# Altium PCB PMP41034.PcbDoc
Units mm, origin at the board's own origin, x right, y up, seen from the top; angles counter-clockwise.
Board outline 30 x 15 mm, 2 copper layers (Top Layer, Bottom Layer), stack 1.575 mm thick; 22 components, 16 nets, 63 pads, 18 vias.
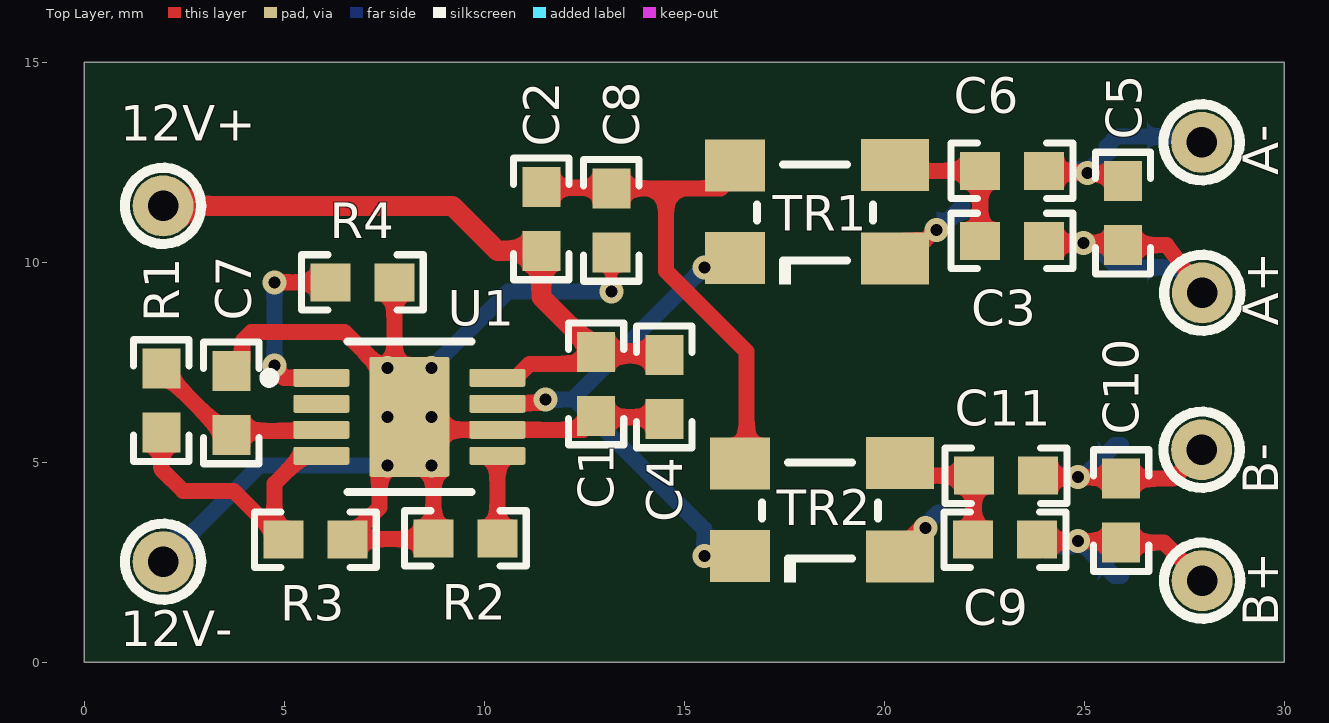
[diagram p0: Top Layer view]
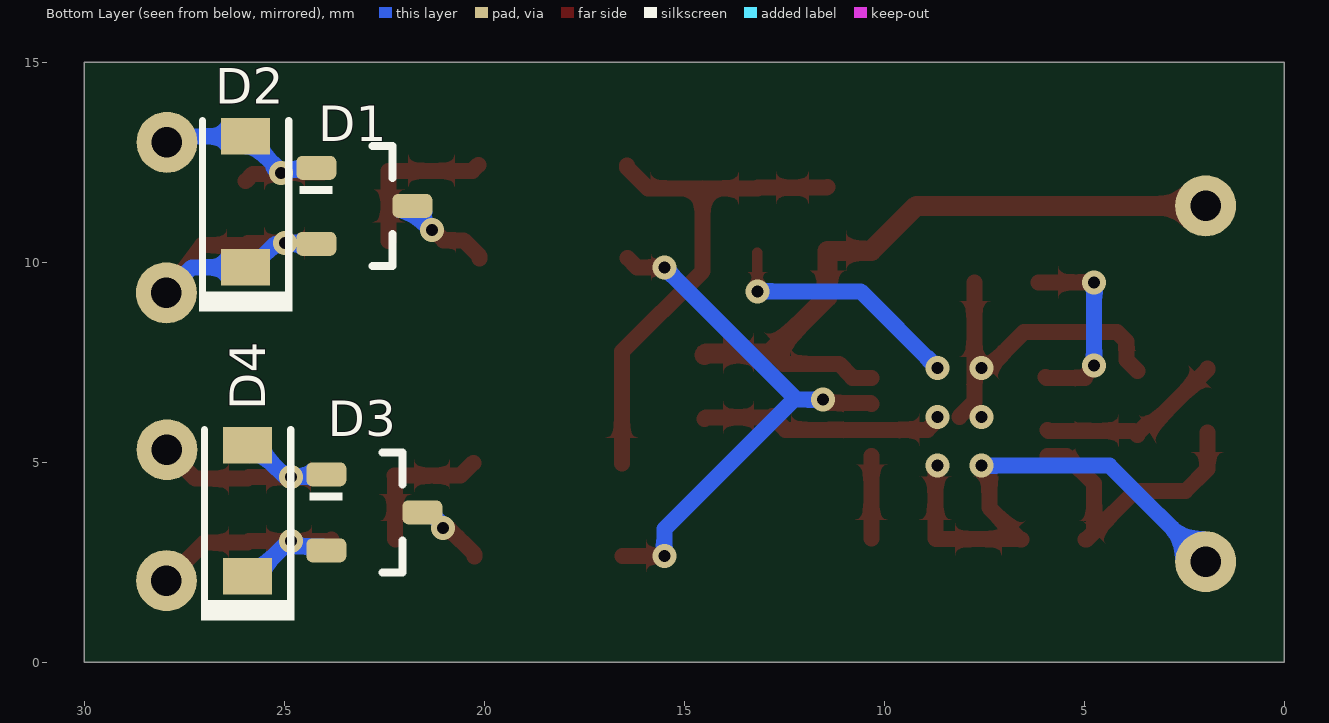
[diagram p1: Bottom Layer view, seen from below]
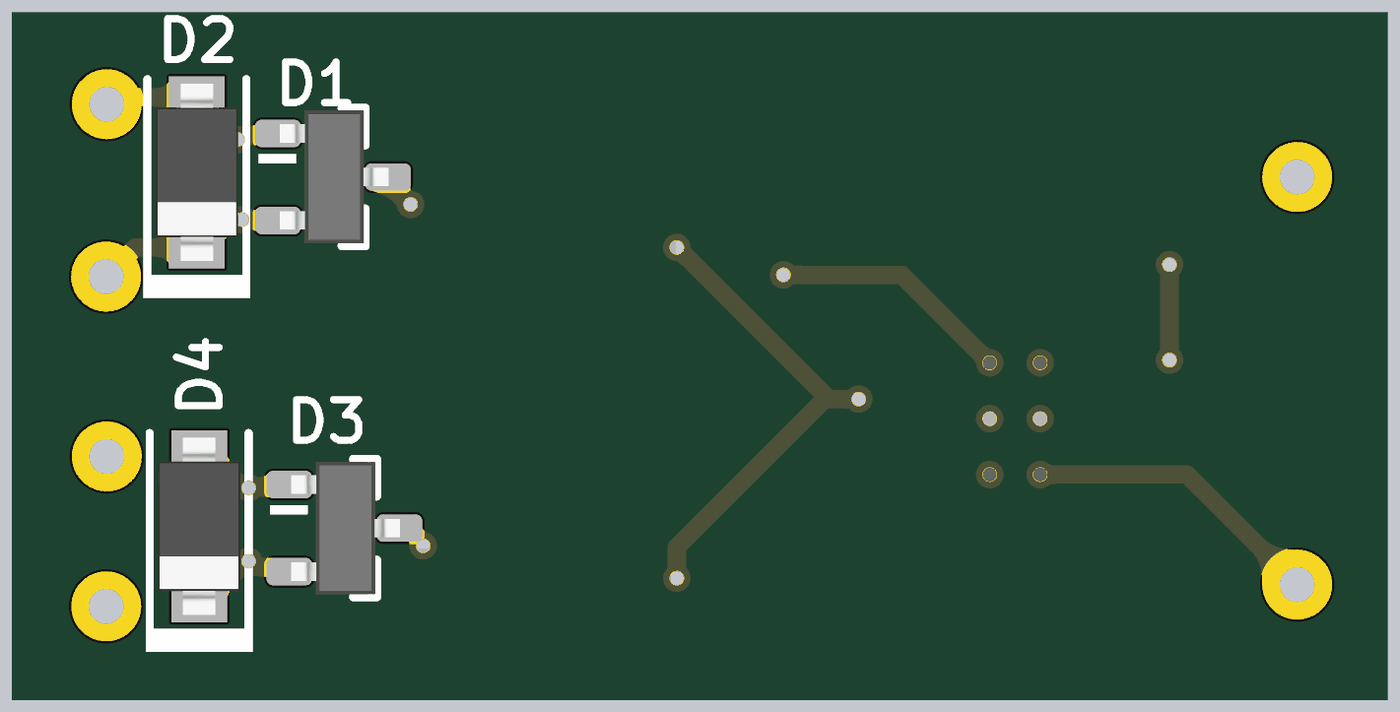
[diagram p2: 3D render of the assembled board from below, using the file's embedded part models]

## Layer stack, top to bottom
Top Solder: solder mask 0.0102, Solder Resist, Dk 3.5
Top Layer: signal copper 0.0356
Dielectric1: core 1.5037, FR-4 High Tg, Dk 4.8
Bottom Layer: signal copper 0.0356
Bottom Solder: solder mask 0.0102, Solder Resist, Dk 3.5

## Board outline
0,0 30,0 30,15 0,15

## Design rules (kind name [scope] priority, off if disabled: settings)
AcuteAngle [All] p1: minimum=4.50000000000000E+0001 checktracksonly=FALSE
AssemblyTestPointUsage [All] p1: valid=2
BoardOutlineClearance BoardOutlineClearance_MountingHoles [OnCopper and InComponentClass('Mounting Holes')] p1: gap=1 ignorepadtopadclearanceinfootprint=FALSE
BoardOutlineClearance BoardOutlineClearance_Poly [OnCopper and IsPoly] p2: gap=0.635 ignorepadtopadclearanceinfootprint=FALSE
BoardOutlineClearance [OnCopper and Not InComponentClass('Logo') and not InComponentClass('FiducialMark') and not InRegion(1000,500,4000,800) and not InPoly] p3: gap=1.016 ignorepadtopadclearanceinfootprint=FALSE
Clearance Clearance_Keepouts [((IsTrack Or IsArc) And Not InPoly) And IsFree and IsKeepOut vs ((IsTrack Or IsArc) And Not InPoly) And IsFree and IsKeepOut] p1: gap=0 ignorepadtopadclearanceinfootprint=FALSE
Clearance Clearance_Poly [InPolygon] p2: gap=0.254 ignorepadtopadclearanceinfootprint=TRUE
Clearance Clearance_FiducialMark [IsKeepOut and InComponentClass('FiducialMark') vs IsPad and InComponentClass('FiducialMark')] p3: gap=0 ignorepadtopadclearanceinfootprint=FALSE
Clearance [All] p4: gap=0.2 ignorepadtopadclearanceinfootprint=TRUE
ComponentClearance ComponentClearance_MountingHoles_FiducialMarks [InComponentClass('Mounting Holes') vs InComponentClass('FiducialMark')] p1 off: gap=1.27 collisioncheckmode=3 verticalgap=0.254 showdistances=FALSE
ComponentClearance ComponentClearance_Shunt [InComponentClass('Header') vs InComponentClass('Shunt')] p2 off: gap=0 collisioncheckmode=3 verticalgap=0 showdistances=FALSE
ComponentClearance ComponentClearance_Logo [InComponentClass('Logo')] p3 off: gap=0.762 collisioncheckmode=3 verticalgap=0.254 showdistances=FALSE
ComponentClearance ComponentClearance_ScrewToNut [(HasFootprint('NY PMS 440 0025 PH')) vs (HasFootprint('Keystone_1902C'))] p4 off: gap=0.127 collisioncheckmode=3 verticalgap=0.254 showdistances=FALSE
ComponentClearance ComponentClearance_MountingHoles [InComponentClass('Mounting Holes')] p5 off: gap=2.54 collisioncheckmode=3 verticalgap=2540 showdistances=FALSE
ComponentClearance ComponentClearance_SmallPassives [HasFootprint('0201*') or HasFootprint('0402*') or HasFootprint('0508') or HasFootprint('0603*') or HasFootprint('0612') or HasFootprint('0805*') or HasFootprint('0815*') or HasFootprint('0830*') or HasFootprint('1206*') or HasFootprint('1210*') or HasFootprint('1808*') or HasFootprint('1812*') or HasFootprint('1825*') or HasFootprint('2010*') or HasFootprint('2220*') or HasFootprint('2225*') or HasFootprint('2512*') or HasFootprint('2728*') or HasFootprint('3518*') vs HasFootprint('0201*') or HasFootprint('0402*') or HasFootprint('0508') or HasFootprint('0603*') or HasFootprint('0612') or HasFootprint('0805*') or HasFootprint('0815*') or HasFootprint('0830*') or HasFootprint('1206*') or HasFootprint('1210*') or HasFootprint('1808*') or HasFootprint('1812*') or HasFootprint('1825*') or HasFootprint('2010*') or HasFootprint('2220*') or HasFootprint('2225*') or HasFootprint('2512*') or HasFootprint('2728*') or HasFootprint('3518*')] p6 off: gap=0.38 collisioncheckmode=3 verticalgap=0.254 showdistances=FALSE
ComponentClearance ComponentClearance_THtoSMT [IsThruComponent vs IsSMTComponent] p7 off: gap=0.762 collisioncheckmode=3 verticalgap=0.762 showdistances=FALSE
ComponentClearance ComponentClearance_THtoTH [IsThruComponent vs IsThruComponent] p8 off: gap=0.508 collisioncheckmode=3 verticalgap=0.762 showdistances=FALSE
ComponentClearance [All] p9 off: gap=0.508 collisioncheckmode=3 verticalgap=0.254 showdistances=FALSE
DiffPairsRouting [All] p1: maxlimit=2.54 minlimit=0.254 mostfreqgap=0.254 toplayer_minwidth=0.381 toplayer_maxwidth=0.381 toplayer_prefwidth=0.381 bottomlayer_minwidth=0.381 bottomlayer_maxwidth=0.381 bottomlayer_prefwidth=0.381 maxuncoupledlength=25.4
FabricationTestPointUsage TestPointUsage [All] p1: valid=2 allowmultiple=FALSE
FabricationTestpoint Testpoint [All] p1: side=3 testpointundercomponent=TRUE minsize=1.016 maxsize=2.54 preferedsize=1.524 minholesize=0 maxholesize=1.016 preferedholesize=0.813 testpointgrid=0.025 allowsidetop=TRUE allowsidebottom=TRUE usegrid=TRUE gridtolerance=0
FanoutControl Fanout_LCC [IsLCC] p1: bgadir=Out bgaviamode=Centered fanoutstyle=Auto fanoutdirection=Alternating viagrid=0.025 // Fanout_LCC (Default Rule)
FanoutControl Fanout_BGA [IsBGA] p2: bgadir=Out bgaviamode=Centered fanoutstyle=Auto fanoutdirection=Alternating viagrid=0.025 // Fanout_BGA (Default Rule)
FanoutControl Fanout_Default [All] p4: bgadir=Out bgaviamode=Centered fanoutstyle=Auto fanoutdirection=Alternating viagrid=0.025 // Fanout_Default (Default Rule)
FanoutControl Fanout_Small [(CompPinCount < 5)] p5: bgadir=Out bgaviamode=Centered fanoutstyle=Auto fanoutdirection=OutThenIn viagrid=0.025 // Fanout_Small (Default Rule)
Height [All] p1 off: minheight=0 maxheight=25.4 prefheight=12.7
HoleSize [All] p1: absolutevalues=TRUE maxlimit=6.375 minlimit=0.2 maxpercent=80.000 minpercent=20.000
MinimumAnnularRing MinimumAnnularRing_ThermalPadVias [IsVia and InAnyComponent] p1: minimumring=0.15
MinimumAnnularRing [All] p2: minimumring=0.1
MinimumSolderMaskSliver MinimumSolderMaskSliver_Logo [InComponentClass('Logo') vs InComponentClass('Logo')] p1: minsoldermaskwidth=0.018
MinimumSolderMaskSliver [All] p2: minsoldermaskwidth=0.1
PlaneConnect [All] p1: planeconnectstyle=Relief reliefexpansion=0.254 reliefentries=4 reliefconductorwidth=0.254 reliefairgap=0.254
PolygonConnect [All] p1: connectstyle=Relief reliefconductorwidth=0.254 reliefentries=4 polygonreliefangle="90 Angle" airgapwidth=0.254
RoutingVias ThermalPadVias [IsVia and InAnyComponent] p1: holewidth=0.2 width=0.5 viastyle="Through Hole" minholewidth=0.2 minwidth=0.5 maxholewidth=0.33 maxwidth=0.6
RoutingVias [All] p2: holewidth=0.406 width=0.864 viastyle="Through Hole" minholewidth=0.2 minwidth=0.5 maxholewidth=1.016 maxwidth=1.651
SilkToBoardRegionClearance [Not ((IsComment or IsDesignator) And (Hide <> 'False')) and not InRegion(1000,500,4000,800)] p1:
SilkToSilkClearance SilkToSilkClearance_Pb-FreeLogo [(HasFootprint('Pb-Free_Overlay_Medium') OR HasFootprint('Pb-Free_Overlay_Small')) vs (HasFootprint('Pb-Free_Overlay_Medium') OR HasFootprint('Pb-Free_Overlay_Small'))] p1: silktosilkclearance=0
SilkToSilkClearance [All] p2: silktosilkclearance=0.1
SilkToSolderMaskClearance SilkToComponentPadClearance [(IsPad or IsFill or IsRegion) and InAnycomponent] p1: minsilkscreentomaskgap=0.127 clearancetoexposedcopper=TRUE
SilkToSolderMaskClearance "Silk to Solder Mask Opening" [All] p2: minsilkscreentomaskgap=0.1 clearancetoexposedcopper=FALSE
SolderMaskExpansion [All] p1: expansion=0.05 istentingtop=FALSE
UnRoutedNet [All] p1: checkbadconnections=TRUE
Width [All] p1: maxlimit=2.54 minlimit=0.152 preferedwidth=0.254 checkconnectedcopper=TRUE
13 further rules are at their usual default settings.

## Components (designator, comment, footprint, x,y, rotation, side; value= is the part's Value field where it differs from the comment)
C1 "GRM188R6YA106MA73D" 0603 12.794,6.963 r270 top value=10uF
C2 "GMK107AB7105KAHT" 0603 11.425,11.087 r90 top value=1uF
C3 "GRM188R71H333KA61D" 0603 23.193,10.537 r180 top value=0.033uF
C4 "EMK107BB7225MA-T" 0603 14.5,6.888 r270 top value=2.2uF
C5 "GRM188R6YA106MA73D" 0603 25.968,11.227 r90 top value=10uF
C6 "GRM188R71H333KA61D" 0603 23.193,12.287 r0 top value=0.033uF
C7 "GMK107AB7105KAHT" 0603 3.675,6.488 r90 top value=1uF
C8 "GMK107AB7105KAHT" 0603 13.175,11.05 r270 top value=1uF
C9 "GRM188R71H333KA61D" 0603 23.019,3.065 r180 top value=0.033uF
C10 "GRM188R6YA106MA73D" 0603 25.919,3.79 r90 top value=10uF
C11 "GRM188R71H333KA61D" 0603 23.044,4.665 r0 top value=0.033uF
D1 "BAT54S-7-F" SOT-23 23,11.412 r180 bottom value=30V
D2 "MMSZ4703-E3-08" SOD-123 25.968,11.512 r90 bottom value=16V
D3 "BAT54S-7-F" SOT-23 22.75,3.75 r180 bottom value=30V
D4 "MMSZ4703-E3-08" SOD-123 25.919,3.79 r90 bottom value=16V
R1 "ERJ3EKF1602V" 0603 1.925,6.541 r90 top value=16.0k
R2 "RC0603FR-0791KL" 0603 9.525,3.098 r0 top value=91.0k
R3 "ERJ3EKF1602V" 0603 5.775,3.065 r180 top value=16.0k
R4 "CRCW060351R1FKEA" 0603 6.951,9.5 r180 top value=51.1
TR1 "4532" SL4532 18.269,11.25 r0 top (schematic designator TRAN1)
TR2 "4532" SL4532 18.395,3.8 r0 top (schematic designator TRAN2)
U1 "UCC25800DGNRQ1" DGN0008G-MFG 8.125,6.138 r0 top

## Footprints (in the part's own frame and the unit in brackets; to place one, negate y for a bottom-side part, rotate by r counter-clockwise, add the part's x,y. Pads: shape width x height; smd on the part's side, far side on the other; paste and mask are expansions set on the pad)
0603 [mm] "0603 from SM-752 data"
  rect 1x0.95 smd: 1(-0.8,0) 2(0.8,0)
  silkscreen extent -1.52,-0.69 1.52,0.69, body extent -0.87,-0.47 0.87,0.47, height 1
DGN0008G-MFG [mm]
  rrect22% 1.4x0.45 smd paste+0 mask+0: 1(-2.2,0.975) 2(-2.2,0.325) 3(-2.2,-0.325) 4(-2.2,-0.975) 5(2.2,-0.975) 6(2.2,-0.325) 7(2.2,0.325) 8(2.2,0.975)
  rrect5% 2x3 smd paste-1000 mask-1000: 9(0,0)
  silkscreen extent -3.62,-1.88 1.55,1.88, body extent -3,-1.8 3,1.8, height 0.25
SL4532 [mm] "SMD, 4-Leads, Body 4.5 x 3.2mm"
  rect 1.5x1.3 smd: 1(-2,-1.141) 2(-2,1.173)
  rect 1.7x1.3 smd: 3(2,1.187) 4(2,-1.15)
  silkscreen extent -1.45,-1.8 1.45,1.2, body extent -2.25,-1.6 2.25,1.6, height 3.45
SOD-123 [mm] "On Semi recommended land pattern"
  rect 0.915x1.22 smd: 1(-1.637,0) 2(1.637,0)
  silkscreen extent -2.74,-1.17 2.03,1.17, body extent -1.93,-0.9 1.93,0.9, height 1.35
SOT-23 [mm] "SOT23, 3-Leads, Body 2.9x1.3mm, Pitch 0.95mm, Lead Span 2.5mm, IPC Medium Density"
  rrect50% 1x0.6 smd: 1(-1.2,0.95) 2(-1.2,-0.95) 3(1.2,0)
  silkscreen extent -1.62,-1.5 0.7,1.5, body extent -1.16,-1.45 1.21,1.45, height 1

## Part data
C1 C5 C10: library part CMP-0007355-6, "CAP, CERM, 10 uF, 35 V, +/- 20%, X5R, 0603", Cap_Case=0603, Manufacturer=Murata, TempCo=X5R, Tolerance_%=20%, Value1=Unknown, Value2=35V, ValueDisplayed=10uF
C2 C7 C8: library part CMP-0007149-4, "CAP, CERM, 1 uF, 35 V, +/- 10%, X7R, AEC-Q200 Grade 0, 0603", Cap_Case=0603, Manufacturer="Taiyo Yuden", Supplier Part Number 1=587-3352-1-ND, TempCo=X7R, Tolerance_%=10%, Value1=Unknown, Value2=35V, ValueDisplayed=1uF
C3 C6 C9 C11: library part CMP-0007451-4, "CAP, CERM, 0.033 uF, 50 V, +/- 10%, X7R, 0603", Cap_Case=0603, Manufacturer=MuRata, Supplier Part Number 1=490-3286-1-ND, TempCo=X7R, Tolerance_%=10%, Value1=Unknown, Value2=50V, ValueDisplayed=0.033uF
C4: library part CMP-0064934-4, "CAP, CERM, 2.2 uF, 16 V,+/- 10%, X7R, 0603", Cap_Case=0603, Manufacturer="Taiyo Yuden", Supplier Part Number 1=587-4864-1-ND, TempCo=X7R, Tolerance_%=10%, Value1=Unknown, Value2=16V, ValueDisplayed=2.2uF
D1 D3: library part CMP-0028456-1, "Diode, Schottky, 30 V, 0.2 A, SOT-23", Manufacturer="Diodes Inc.", Supplier Part Number 1=BAT54S-FDICT-ND, Value1=0.2A, Value2=0.65V
D2 D4: library part CMP-0077613-3, "Diode, Zener, 16 V, 500 mW, SOD-123", Manufacturer=Vishay-Semiconductor, Power_W=500mW, Value1=0.5W
R1 R3: library part CMP-0078661-1, "RES, 16.0 k, 1%, 0.1 W, AEC-Q200 Grade 0, 0603", Manufacturer=Panasonic, Power_W=100mW, Supplier Part Number 1=P16.0KHCT-ND, TempCo="100 ppm/C", Tolerance_%=1%, Value2=0.1W, Value_Code=16k0, ValueDisplayed=16.0k
R2: library part CMP-0023318-5, "RES, 91.0 k, 1%, 0.1 W, 0603", Manufacturer=Yageo, Power_W=100mW, Supplier Part Number 1=311-91.0KHRCT-ND, TempCo="100 ppm/C", Tolerance_%=1%, Value2=0.1W, Value_Code=91k0, ValueDisplayed=91.0k
R4: library part CMP-0022483-4, "RES, 51.1, 1%, 0.1 W, AEC-Q200 Grade 0, 0603", Manufacturer=Vishay-Dale, Power_W=100mW, Supplier Part Number 1=541-51.1HCT-ND, TempCo="100 ppm/C", Tolerance_%=1%, Value2=0.1W, Value_Code=51R1, ValueDisplayed=51.1
TR1 TR2: library part SL4532, "Tranformer 4.5mm x 3.2mm, 3.45mm height"
U1: library part CMP-0088494-2, "Open Loop LLC Transformer Driver for Isolated Bias Supplies", Manufacturer="Texas Instruments", Max Supply Voltage=36V, Min Supply Voltage=12V, Nominal Supply Current=500uA, Operating Temperature Range="-40°C to +150°C", Switching Frequency=100-2000kHz

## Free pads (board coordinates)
  round 1.524 hole 0.762: 4(1.968,11.412) 4(27.934,5.314) 4(27.934,13) 4(27.946,2.042) 4(27.948,9.237) 5(1.968,2.516)

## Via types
v1: diameter 0.6, hole 0.3, Top Layer to Bottom Layer, tented both sides, 18 vias

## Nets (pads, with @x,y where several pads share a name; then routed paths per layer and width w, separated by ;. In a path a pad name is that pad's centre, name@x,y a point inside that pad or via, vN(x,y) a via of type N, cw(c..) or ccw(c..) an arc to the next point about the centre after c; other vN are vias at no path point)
12V: C1.1 C2.1 C4.1 pad.4@1.968,11.412 U1.8 | length 17.5
  Top Layer w0.4: U1.8 10.8,7.113 10.825,7.138 10.825,7.156 11.132,7.463 12.519,7.463 12.794,7.738 C1.1
  Top Layer w0.5: pad.4@1.968,11.412 9.2,11.412 10.325,10.287 C2.1 11.425,9.132 12.544,8.013 12.569,8.013 12.794,7.788 C1.1 12.832,7.725 14.462,7.725 C4.1
GND: C1.2 C4.2 C7.2 C8.2 pad.5 R2.1 R3.1 R4.1 U1.6 U1.9 | length 33.8
  Top Layer w0.254: v1(13.175,9.277) C8.2
  Top Layer w0.4: C7.2 3.95,7.563 3.95,8.025 4.184,8.259 6.503,8.259 7.405,7.358 v1(7.575,7.358) ; R3.1 6.6,3.065 R3.1@6.616,3.081 ; v1(7.575,4.918) 7.455,4.918 7.375,4.838 7.375,3.865 6.875,3.365 6.875,3.34 R3.1@6.616,3.081 ; R4.1 7.751,7.358 7.751,6.512 U1.9 ; v1(8.675,4.918) 8.725,4.868 R2.1 8.709,3.081 R3.1@6.616,3.081 ; v1(8.675,6.138) 8.675,6.063 8.925,5.813 U1.6 12.469,5.813 12.794,6.138 C1.2 12.832,6.125 14.462,6.125 C4.2
  Bottom Layer w0.4: pad.5 4.37,4.918 v1(7.575,4.918) ; v1(8.675,7.358) 10.594,9.277 v1(13.175,9.277)
  other v1: 7.575,6.138
GNDH: C5.2 C6.2 D1.1 D2.2 pad.4@27.934,13 | length 7.3
  Top Layer w0.4: C6.2 24.032,12.247 25.061,12.247 25.099,12.209 25.786,12.209 C5.2
  Bottom Layer w0.4: D1.1 24.242,12.319 24.962,12.319 25.053,12.228 v1(25.08,12.228) 25.099,12.247 25.154,12.247 25.275,12.369 25.275,12.456 25.558,12.739 25.558,12.892 D2.2@25.815,13.149 ; D2.2 D2.2@25.815,13.149 ; pad.4@27.934,13 27.946,13.544 27.551,13.149 D2.2@25.815,13.149
GNDL: C10.2 C11.2 D3.1 D4.2 pad.4@27.934,5.314 | length 6.8
  Top Layer w0.4: C11.2 23.881,4.628 v1(24.839,4.628) 25.881,4.628 C10.2 27.222,4.59 27.946,5.314 pad.4@27.934,5.314
  Bottom Layer w0.4: D3.1 24.003,4.647 24.82,4.647 v1(24.839,4.628) 24.858,4.647 24.985,4.647 25.766,5.428 D4.2
NetC2_2: C2.2 C8.1 TR1.2 TR2.2 | length 13
  Top Layer w0.4: C2.2 11.444,11.868 13.156,11.868 C8.1 14.543,11.85 ; TR1.2@16.434,12.423 16.434,12.373 15.911,11.85 14.543,11.85 ; TR2.2@16.56,4.973 16.56,7.764 14.543,9.781 14.543,11.85
NetC3_2: C3.2 C6.1 TR1.3 | length 4.1
  Top Layer w0.4: TR1.3@20.148,12.437 20.298,12.287 C6.1 C3.2
NetC7_1: C7.1 R1.2 U1.3 | length 4.8
  Top Layer w0.4: R1.2 1.925,7.316 3.253,5.988 3.4,5.988 3.675,5.713 C7.1 3.775,5.788 5.9,5.788 U1.3
NetC9_2: C9.2 C11.1 TR2.3 | length 3.7
  Top Layer w0.4: TR2.3@20.274,4.987 20.596,4.665 C11.1 22.231,4.653 22.231,3.078 C9.2
NetD1_3: D1.3 TR1.4 | length 2.4
  Top Layer w0.4: TR1.4@20.119,10.1 20.119,10.15 20.519,10.55 21.017,10.55 21.279,10.812 v1(21.306,10.812)
  Bottom Layer w0.4: v1(21.306,10.812) 21.326,10.831 21.369,10.831 D1.3@21.95,11.412
NetD3_3: D3.3 TR2.4 | length 1.6
  Top Layer w0.4: TR2.4@20.245,2.65 20.245,2.7 20.888,3.344 21.013,3.344 v1(21.032,3.363)
  Bottom Layer w0.4: v1(21.032,3.363) 21.051,3.382 21.051,3.451 D3.3@21.35,3.75
NetR1_1: R1.1 R3.2 U1.4 | length 7.4
  Top Layer w0.4: R1.1 1.925,4.828 2.47,4.283 3.732,4.283 R3.2@4.754,3.261 ; R3.2 4.95,3.065 R3.2@4.754,3.261 ; U1.4 5.45,5.163 4.754,4.467 R3.2@4.754,3.261
NetR2_2: R2.2 U1.5 | length 2.1
  Top Layer w0.4: R2.2 U1.5
NetR4_2: R4.2 U1.1 | length 4.9
  Top Layer w0.4: v1(4.754,9.5) R4.2 ; v1@4.758,7.416 v1(4.754,7.416) 4.754,7.389 4.989,7.155 4.989,7.113 U1.1 5.95,7.113 U1.1@5.975,7.138
  Bottom Layer w0.4: v1(4.754,7.416) v1(4.754,9.5)
NetTRAN1_1: TR1.1 TR2.1 U1.7 | length 13.9
  Top Layer w0.4: U1.7 10.35,6.488 11.401,6.488 11.479,6.566 v1(11.533,6.566) ; v1(15.5,2.659) TR2.1@16.545,2.659 ; v1(15.5,9.874) 16.185,9.874 TR1.1@16.419,10.108
  Bottom Layer w0.4: v1(11.533,6.566) 12.266,6.566 15.5,3.332 v1(15.5,2.659) ; 12.23,6.604 v1(15.5,9.874)
VH: C3.1 C5.1 D1.2 D2.1 pad.4@27.948,9.237 | length 8.9
  Top Layer w0.4: C3.1 24.048,10.482 v1(24.98,10.482) 25.913,10.482 C5.1 27.06,10.427 pad.4@27.948,9.237
  Bottom Layer w0.4: D1.2 24.21,10.472 24.97,10.472 v1(24.98,10.482) 25,10.463 25.227,10.463 25.815,9.874 D2.1 27.309,9.874 27.946,9.237 pad.4@27.948,9.237
VL: C9.1 C10.1 D3.2 D4.1 pad.4@27.946,2.042 | length 8.3
  Top Layer w0.4: C9.1 23.856,3.028 v1(24.839,3.028) 25.881,3.028 C10.1 26.998,2.99 pad.4@28.035,1.953 ; pad.4@28.035,1.953 28.035,1.77 27.946,2.042 28.25,1.738 pad.4@28.035,1.953
  Bottom Layer w0.4: D3.2 24.05,2.9 24.684,2.9 24.812,3.028 v1(24.839,3.028) 24.858,3.009 24.91,3.009 25.766,2.153 D4.1
pads on no net: U1.2

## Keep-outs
Keep-Out Layer:
  text ".Layer_Name" at 14.656,-21.806 h1.52

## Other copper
Top Layer:
  text ".Layer_Name" at 14.656,-21.806 h1.52
Bottom Layer:
  text ".Layer_Name" at 14.656,-21.806 h1.52

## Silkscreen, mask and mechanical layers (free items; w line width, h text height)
Top Overlay:
  circle w0.254: c27.946,2.042 r0.954
  circle w0.254: c27.934,5.314 r0.954
  circle w0.254: c27.948,9.237 r0.954
  circle w0.254: c27.934,13 r0.954
  circle w0.254: c1.968,2.516 r0.954
  circle w0.254: c1.968,11.412 r0.954
  text "12V+" at 0.902,13.043 h0.89
  text "A-" at 29.848,12.18 h0.89 r90
  text "A+" at 29.848,8.412 h0.89 r90
  text "B-" at 29.848,4.202 h0.89 r90
  text "B+" at 29.848,0.902 h0.89 r90
  text "12V-" at 0.902,0.402 h0.89
  text ".Layer_Name" at 14.656,-21.806 h1.52
Bottom Overlay:
  text ".Layer_Name" at 14.656,-21.806 h1.52
Top Paste:
  text ".Layer_Name" at 14.656,-21.806 h1.52
Bottom Paste:
  text ".Layer_Name" at 14.656,-21.806 h1.52
Top Solder:
  text ".Layer_Name" at 14.656,-21.806 h1.52
  text ".Layer_Name" at 14.656,-21.806 h1.52
Bottom Solder:
  text ".Layer_Name" at 14.656,-21.806 h1.52
Drill Guide:
  text ".Layer_Name" at 14.656,-21.806 h1.52
M1 Board Outline:
  the board outline again, w0.2
  text ".Layer_Name" at 14.656,-21.806 h1.52
M2 Board Dimensions:
  rectangle: 0,-6.985 3.175,-3.81
  rectangle: 3.175,-10.16 12.7,-6.985
  lines w0.178: 0,-6.985 25.4,-6.985 ; 3.175,-10.16 3.175,-3.81 ; 6.35,-10.16 6.35,-3.81 ; 12.7,-10.16 12.7,-3.81 ; 19.05,-10.16 19.05,-3.81 ; 0,-10.16 25.4,-10.16 25.4,-3.81 0,-3.81 0,-10.16
  text ".Layer_Name" at 14.656,-21.806 h1.52
M3 3D STEP Top:
  text ".Layer_Name" at 14.656,-21.806 h1.52
M4 3D STEP Bottom:
  text ".Layer_Name" at 14.656,-21.806 h1.52
M5 Assembly Top:
  lines w0.254: -7.417,-23.626 160.223,-23.626 ; -7.417,-18.462 160.274,-18.462 ; -7.417,-13.297 -7.417,-28.791 94.31,-28.791 160.274,-28.791 160.274,-13.297 -7.404,-13.297 -7.404,-28.791 32.614,-28.791 ; 55.194,-28.791 55.194,-13.297 ; 87.376,-18.462 87.376,-13.297 ; 108.712,-18.462 108.712,-13.297 ; 124.511,-28.956 124.511,-23.804
  text "COMPONENTS MARKED 'DNP' SHOULD NOT BE POPULATED." at 29.299,-8.09 h1.52
  text "ASSEMBLY VARIANT:" at 29.286,-11.024 h1.52
  text ".VariantName" at 55.601,-11.024 h1.52
  text "PCB VIEWED FROM TOP SIDE" at -5.804,-16.654 h1.52
  text "BOARD #:" at 57.099,-16.654 h1.52
  text ".PRJ_Number" at 70.955,-16.654 h1.52
  text "REV:" at 92.405,-16.654 h1.52
  text ".PCB_Rev" at 99.809,-16.654 h1.52
  text "SVN REV:" at 113.69,-16.654 h1.52
  text ".VersionControl_RevNumber" at 126.543,-16.654 h1.52
  text "TID #:" at 57.099,-21.819 h1.52
  text ".TID" at 70.955,-21.819 h1.52
  text "PLOT NAME =" at -5.804,-27.034 h1.52
  text ".plot_File_Name" at 14.656,-27.034 h1.52
  text "GENERATED    :" at 57.15,-27.034 h1.52
  text ".Print_Date" at 79.235,-27.034 h1.52
  text ".Print_Time" at 97.752,-27.034 h1.52
  text "TEXAS INSTRUMENTS" at 129.87,-27.034 h1.52
M6 Assembly Bottom:
  lines w0.254: -7.429,-18.474 160.261,-18.474 ; -7.379,-23.639 160.261,-23.639 ; 28.334,-28.969 28.334,-23.817 ; 44.133,-18.474 44.133,-13.31 ; 65.468,-18.474 65.468,-13.31 ; 97.65,-28.804 97.65,-13.31 ; 120.231,-28.804 160.249,-28.804 160.249,-13.31 -7.429,-13.31 -7.429,-28.804 58.534,-28.804 160.261,-28.804 160.261,-13.31
  text "COMPONENTS MARKED 'DNP' SHOULD NOT BE POPULATED." at 154.991,-8.077 h1.52
  text ".VariantName" at 128.473,-11.024 h1.52
  text "ASSEMBLY VARIANT:" at 154.864,-11.024 h1.52
  text ".VersionControl_RevNumber" at 26.302,-16.667 h1.52
  text "SVN REV:" at 39.154,-16.667 h1.52
  text ".PCB_Rev" at 53.035,-16.667 h1.52
  text "REV:" at 60.439,-16.667 h1.52
  text ".PRJ_Number" at 81.89,-16.667 h1.52
  text "BOARD #:" at 95.745,-16.667 h1.52
  text "PCB VIEWED FROM BOTTOM SIDE" at 158.648,-16.667 h1.52
  text ".TID" at 81.89,-21.831 h1.52
  text "TID #:" at 95.745,-21.831 h1.52
  text "TEXAS INSTRUMENTS" at 22.974,-27.047 h1.52
  text ".Print_Time" at 55.093,-27.047 h1.52
  text ".Print_Date" at 73.609,-27.047 h1.52
  text "GENERATED    :" at 95.694,-27.047 h1.52
  text ".plot_File_Name" at 138.189,-27.047 h1.52
  text "PLOT NAME =" at 158.648,-27.047 h1.52
M9 Title Sheet:
  drawing of 57 lines, arcs and shapes, not listed
  text "1" at 18.792,204.127 h1.78
  text "2" at 82.182,204.127 h1.78
  text "3" at 145.411,204.127 h1.78
  text "4" at 209.08,204.127 h1.78
  text "5" at 272.555,204.127 h1.78
  text "6" at 336.182,204.127 h1.78
  text "A" at -10.579,175.095 h1.78
  text "A" at 365.341,175.095 h1.78
  text "B" at -10.579,114.643 h1.78
  text "B" at 365.341,114.643 h1.78
  text "C" at -10.579,54.318 h1.78
  text "C" at 365.341,54.318 h1.78
  text "PROJECT TITLE:" at 288.125,7.048 h1.14
  text ".PRJ_Title" at 289.395,3.662 h1.78
  text "DESIGNED FOR:" at 288.125,-0.597 h1.14
  text ".PRJ_Customer" at 289.395,-4.153 h1.78
  text "D" at -10.579,-5.88 h1.78
  text "D" at 365.341,-5.88 h1.78
  text "FILE NAME:" at 288.125,-8.217 h1.14
  text ".PCB_File_Name_No_Path" at 289.395,-11.265 h1.78
  text "Texas Instruments (TI) and/or its licensors do not warrant the accuracy or completeness of this specification" at 161.9,-15.376 h1.14
  text "ENGINEER:" at 288.125,-15.583 h1.14
  text "LAYOUT BY:" at 326.352,-15.583 h1.14
  text "or any information contained therein. TI and/or its licensors do not warrant that this design will meet" at 160.757,-18.237 h1.14
  text ".PRJ_Engineer" at 289.395,-19.52 h1.78
  text ".PCB_Layout" at 327.635,-19.52 h1.78
  text "the specifications, will be suitable for your application or fit for any particular purpose, or will operate in" at 160.757,-21.099 h1.14
  text ".Layer_Name" at 14.656,-21.806 h1.52
  text "ALTIUM DESIGNER VERSION:" at 326.352,-23.457 h1.14
  text "an implementation. TI and/or its licensors do not warrant that the design is production worthy. You should" at 160.757,-23.961 h1.14
  text "completely validate and test your design implementation to confirm the system functionality for your application." at 161.9,-26.822 h1.14
  text ".print_Scale" at 289.395,-26.843 h1.78
  text ".Application_BuildNumber" at 327.635,-26.843 h1.78
  text "1" at 18.792,-32.093 h1.78
  text "2" at 82.182,-32.093 h1.78
  text "3" at 145.411,-32.093 h1.78
  text "4" at 209.08,-32.093 h1.78
  text "5" at 272.555,-32.093 h1.78
  text "6" at 336.182,-32.093 h1.78
M10 Fab Notes:
  drawing of 189 lines, arcs and shapes, not listed
  text "DESIGN INFORMATION" at 314.503,161.447 h1.52
  text "MIN. TRACK WIDTH:" at 298.131,158.091 h1.52
  text "8" at 325.976,158.091 h1.52
  text "MIL" at 329.907,158.091 h1.52
  text "7.874" at 321.75,155 h1.52
  text "MIN. CLEARANCE:" at 298.131,154.938 h1.52
  text "MIL" at 329.907,154.938 h1.52
  text "MIN. VIA PAD SIZE:" at 298.131,151.785 h1.52
  text "24" at 325.214,151.785 h1.52
  text "MIL" at 329.907,151.785 h1.52
  text "0.05mm (2MIL)" at 315.784,148.486 h1.52
  text "MINIMUM ANNULAR RING" at 289.769,148.277 h1.52
  text "EXTERNAL" at 333.768,148.277 h1.52
  text "PER" at 294.849,145.48 h1.52
  text "IPC-D-275 CLASS 2 LEVEL C" at 300.437,145.48 h1.52
  text "MIL, HOLES" at 338.238,142.928 h1.52
  text "+/-" at 328.27,142.709 h1.52
  text "+/-" at 349.961,142.709 h1.52
  text "REGISTRATION TOLERANCES:" at 289.769,142.682 h1.52
  text "METAL" at 320.243,142.682 h1.52
  text "5" at 334.879,142.683 h1.52
  text "3" at 356.037,142.683 h1.52
  text "MIL" at 358.99,142.682 h1.52
  text "HOLE SIZE TOLERANCE (UNLESS OTHERWISE SPECIFIED):" at 289.769,140.185 h1.52
  text "+/-" at 349.961,140.112 h1.52
  text "3" at 356.037,140.085 h1.52
  text "MIL" at 358.99,140.085 h1.52
  text "MATERIAL:" at 287.87,136.589 h1.52
  text "FR-4 High Tg" at 312.926,133.324 h1.52
  text "X" at 309.257,133.122 h1.52
  text "FR-408" at 298.563,133.007 h1.52
  text "OTHER" at 336.358,133.007 h1.52
  text "62 MIL (1.6mm) +/-10%" at 306.694,129.374 h1.52
  text "X" at 303.643,129.312 h1.52
  text "THICKNESS:" at 289.769,129.165 h1.52
  text "OTHER" at 339.33,129.165 h1.52
  text "TOLERANCE:" at 289.769,125.652 h1.52
  text "X" at 311.314,125.652 h1.52
  text "ANSI IPC-6012 TYPE 3 CLASS 2" at 315.836,125.652 h1.52
  text "OTHER +/-" at 315.835,121.989 h1.52
  text "BOW & TWIST:" at 289.769,118.302 h1.52
  text "X" at 311.314,118.302 h1.52
  text "ANSI IPC-6012 TYPE 3 CLASS 2" at 315.836,118.302 h1.52
  text "OTHER +/-" at 315.835,114.576 h1.52
  text "DRILLING:" at 287.87,111.258 h1.52
  text "NC_DRILL FILES" at 332.599,108.586 h1.52
  text "REFERENCE:" at 289.769,108.486 h1.52
  text "X" at 306.463,108.484 h1.52
  text "AS SHOWN" at 310.984,108.486 h1.52
  text "X" at 329.348,108.486 h1.52
  text "OTHER" at 340.168,104.873 h1.52
  text "PTH COPPER THICKNESS:" at 289.761,104.783 h1.52
  text "X" at 318.697,104.783 h1.52
  text "20-30 um" at 321.948,104.783 h1.52
  text "BOARD FINISH:" at 287.87,101.034 h1.52
  text "SILKSCREEN:" at 291.812,98.237 h1.52
  text "X" at 316.14,98.237 h1.52
  text "TOP" at 319.112,98.237 h1.52
  text "X" at 329.094,98.237 h1.52
  text "BOTTOM" at 332.091,98.237 h1.52
  text "SILKSCREEN COLOR:" at 291.812,94.295 h1.52
  text "X" at 316.115,94.295 h1.52
  text "WHITE" at 319.112,94.295 h1.52
  text "OTHER" at 332.091,94.295 h1.52
  text "X" at 319.442,90.652 h1.52
  text "GREEN" at 322.439,90.652 h1.52
  text "OTHER" at 338.136,90.652 h1.52
  text "SOLDER RESIST COLOR:" at 291.812,90.477 h1.52
  text "X" at 319.442,86.734 h1.52
  text "MATTE" at 322.439,86.734 h1.52
  text "SEMI-GLOSS" at 338.125,86.717 h1.52
  text "IMMERSION GOLD (ENIG)" at 314.819,82.345 h1.52
  text "ENEPIG" at 348.793,82.162 h1.52
  text "SURFACE FINISH:" at 287.87,82.136 h1.52
  text "X" at 310.298,82.136 h1.52
  text "IMM. TIN/SILVER OR EQUIV" at 296.24,78.649 h1.52
  text "OTHER" at 332.599,78.549 h1.52
  text "ARRAY/PANEL:" at 287.87,74.602 h1.52
  text "CUT AND TRIM PER M1 BOARD OUTLINE" at 314.819,74.393 h1.52
  text "N.C. ROUTE" at 314.819,70.94 h1.52
  text "X" at 332.295,70.94 h1.52
  text "V. SCORE" at 336.816,70.94 h1.52
  text "CERTIFICATION:" at 287.87,67.66 h1.52
  text "MATERIALS AND WORKMANSHIP FOR ALL PCBS" at 306.285,67.66 h1.52
  text "TO MEET OR EXCEED THE REQUIREMENTS OF:" at 306.285,65.271 h1.52
  text "X" at 297.078,62.003 h1.52
  text "ANSI IPC-A-600F CLASS ->" at 300.329,62.003 h1.52
  text "X" at 342.188,62.003 h1.52
  text "2" at 344.982,62.003 h1.52
  text "1" at 336.981,61.965 h1.52
  text "3" at 353.973,61.965 h1.52
  text "X" at 317.702,58.252 h1.52
  text "RoHS" at 320.953,58.252 h1.52
  text "OTHER" at 337.321,58.252 h1.52
  text "PER ORDER" at 347.407,58.252 h1.52
  text "ALL BOARDS MUST MEET OR EXCEED UL94-V0 REQUIREMENTS." at 288.569,54.345 h1.52
  text "PCB MUST BEAR THE UL94V-0 UL REGISTERED MATERIAL ID NUMBER" at 288.569,51.397 h1.52
  text "ADDITIONAL REQUIREMENTS:" at 287.87,47.094 h1.52
  text "MICROSECTION:" at 289.769,44.373 h1.52
  text "YES" at 312.775,44.373 h1.52
  text "REQUIRED" at 334.657,40.707 h1.52
  text "BARE BOARD ELEC. TEST:" at 289.769,40.634 h1.52
  text "NONE" at 322.935,40.634 h1.52
  text "X" at 331.66,40.634 h1.52
  text "PER ORDER" at 349.693,40.634 h1.52
  text "XX MIL VIAS REQUIRE NON-CONDUCTIVE FILL AND PLANARIZE" at 294.04,35.428 h1.5
  text "XX MIL VIAS REQUIRE CONDUCTIVE FILL AND PLANARIZE" at 294.243,32.787 h1.52
  text "OUTER XX MIL TRACES REQUIRE 50 OHM SINGLE-ENDED IMPEDANCE" at 294.218,28.637 h1.47
  text "LAYER 2 & 3 (INNER LAYERS) XX MIL WIDE, XX MIL SPACE / TRACES REQUIRE 100 OHM DIFFERENTIAL IMPEDANCE" at 294.015,22.65 h1.52
  text ".Layer_Name" at 14.656,-21.806 h1.52
M11 Gerber Information:
  lines w0.254: -7.417,-23.626 160.223,-23.626 ; -7.417,-18.462 160.274,-18.462 ; -7.417,-13.297 -7.417,-28.791 94.31,-28.791 160.274,-28.791 160.274,-13.297 -7.404,-13.297 -7.404,-28.791 32.614,-28.791 ; 55.194,-28.791 55.194,-13.297 ; 87.376,-18.462 87.376,-13.297 ; 108.712,-18.462 108.712,-13.297 ; 124.511,-28.956 124.511,-23.804
  text "ALL ARTWORK VIEWED FROM TOP SIDE" at -5.804,-16.654 h1.52
  text "BOARD #:" at 57.099,-16.654 h1.52
  text ".PRJ_Number" at 70.955,-16.654 h1.52
  text "REV:" at 92.405,-16.654 h1.52
  text ".PCB_Rev" at 99.809,-16.654 h1.52
  text "SVN REV:" at 113.69,-16.654 h1.52
  text ".VersionControl_RevNumber" at 126.543,-16.654 h1.52
  text "LAYER NAME =" at -5.804,-21.806 h1.52
  text "TID #:" at 57.099,-21.819 h1.52
  text ".TID" at 70.955,-21.819 h1.52
  text "PLOT NAME =" at -5.804,-27.034 h1.52
  text ".plot_File_Name" at 14.656,-27.034 h1.52
  text "GENERATED    :" at 57.15,-27.034 h1.52
  text ".Print_Date" at 79.235,-27.034 h1.52
  text ".Print_Time" at 97.752,-27.034 h1.52
  text "TEXAS INSTRUMENTS" at 129.87,-27.034 h1.52
M12 Stackup:
  drawing of 191 lines, arcs and shapes, not listed
  text "Layer" at 249.469,200.023 h1.52
  text "Name" at 259.88,200.023 h1.52
  text "Material" at 283.496,200.023 h1.52
  text "Thickness" at 305.334,200.023 h1.52
  text "Constant" at 321.84,200.023 h1.52
  text "Board Layer Stack" at 336.314,200.023 h1.52
  text "Top Overlay" at 259.88,196.975 h1.52
  text "Top Solder" at 259.88,193.927 h1.52
  text "Solder Resist" at 283.496,193.927 h1.52
  text "0.40mil" at 305.334,193.927 h1.52
  text "3.5" at 321.84,193.927 h1.52
  text "1" at 249.469,190.879 h1.52
  text "Top Layer" at 259.88,190.879 h1.52
  text "1.40mil" at 305.334,190.879 h1.52
  text "Dielectric1" at 259.88,187.831 h1.52
  text "FR-4 High Tg" at 283.496,187.831 h1.52
  text "59.20mil" at 305.334,187.831 h1.52
  text "4.8" at 321.84,187.831 h1.52
  text "2" at 249.469,184.783 h1.52
  text "Bottom Layer" at 259.88,184.783 h1.52
  text "1.40mil" at 305.334,184.783 h1.52
  text "Bottom Solder" at 259.88,181.735 h1.52
  text "Solder Resist" at 283.496,181.735 h1.52
  text "0.40mil" at 305.334,181.735 h1.52
  text "3.5" at 321.84,181.735 h1.52
  text "Bottom Overlay" at 259.88,178.687 h1.52
  text ".Layer_Name" at 14.656,-21.806 h1.52
M13 Component Bodies Top:
  text ".Layer_Name" at 14.656,-21.806 h1.52
M14 Component Bodies Bottom:
  text ".Layer_Name" at 14.656,-21.806 h1.52
M15 Courtyards Top:
  text ".Layer_Name" at 14.656,-21.806 h1.52
M16 Courtyards Bottom:
  text ".Layer_Name" at 14.656,-21.806 h1.52
Drill Drawing:
  circle w0.254: c38.101,6.577 r0.702
  lines w0.254: 37.4,10.436 38.803,10.436 38.101,9.033 37.4,10.436
  lines w0.305: 36.127,4.928 118.207,4.928 ; 36.127,11.243 118.207,11.243 ; 44.709,1.77 44.709,14.401 ; 53.142,1.77 53.142,14.401 ; 69.311,1.77 69.311,14.401 ; 75.893,1.77 75.893,14.401 ; 85.422,1.77 85.422,14.401 ; 103.82,1.77 103.82,14.401 ; 36.127,1.77 118.207,1.77 118.207,14.401 36.127,14.401 36.127,1.77
  text "Symbol" at 38.022,12.191 h1.83
  text "Quantity" at 45.656,12.191 h1.83
  text "Finished Hole Size" at 54.089,12.191 h1.83
  text "Plated" at 70.258,12.191 h1.83
  text "Hole Type" at 76.84,12.191 h1.83
  text "Drill Layer Pair" at 86.369,12.191 h1.83
  text "Hole Tolerance" at 104.767,12.191 h1.83
  text "18" at 45.656,9.033 h1.52
  text "11.81mil (0.300mm)" at 54.089,9.033 h1.52
  text "PTH" at 70.258,9.033 h1.52
  text "Round" at 76.84,9.033 h1.52
  text "Top Layer - Bottom Layer" at 86.369,9.033 h1.52
  text "6" at 45.656,5.875 h1.52
  text "30.00mil (0.762mm)" at 54.089,5.875 h1.52
  text "PTH" at 70.258,5.875 h1.52
  text "Round" at 76.84,5.875 h1.52
  text "Top Layer - Bottom Layer" at 86.369,5.875 h1.52
  text "24 Total" at 45.656,2.718 h1.52
  text ".Layer_Name" at 14.656,-21.806 h1.52
M17 Embedded Cavity:
  text ".Layer_Name" at 14.656,-21.806 h1.52
M18 Embedded Assembly:
  text ".Layer_Name" at 14.656,-21.806 h1.52
M19 Embedded Keepout:
  text ".Layer_Name" at 14.656,-21.806 h1.52

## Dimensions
0,-10.16 to 25.4,-10.16 on M2 Board Dimensions
0,0 to 0,15 on M2 Board Dimensions
0,0 to 30,0 on M2 Board Dimensions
